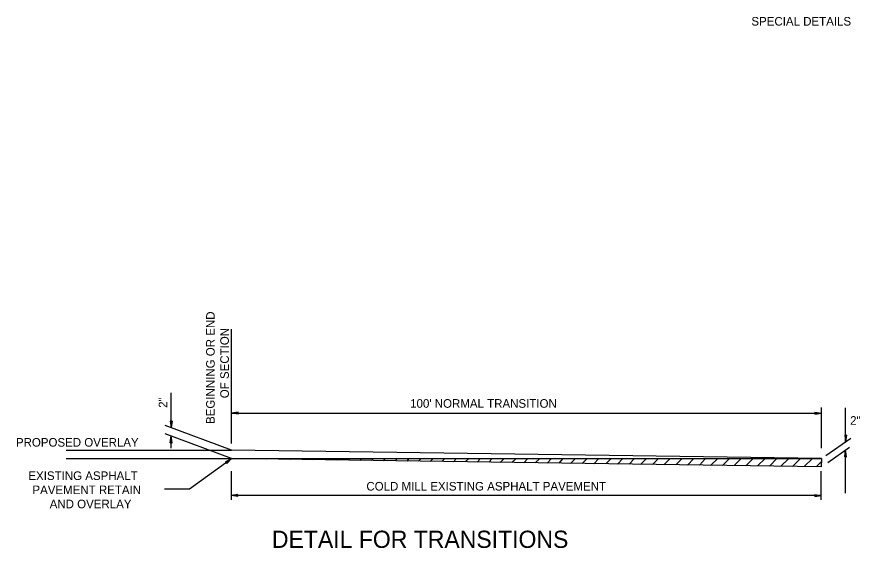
# Model space of a CAD drawing. Extents: x 1955770 to 1955917, y 566446 to 566544.
# Drawn here: x 1955852.8 to 1955911.7, y 566506.9 to 566544 of the extents above; entities that cross this region are included whole.
import ezdxf

# ---------------------------------------------------------------- set-up
doc = ezdxf.new("R2010")
doc.units = 0
doc.layers.add('Default', color=7, linetype='Continuous')
doc.layers.add('STAMP', color=7, linetype='Continuous')

msp = doc.modelspace()

# ---------------------------------------------------------------- linework, layer by layer
at = {"layer": 'Default'}
for p, q in [((1955867.799, 566514.22), (1955867.799, 566522.207)), ((1955863.58, 566515.354), (1955863.58, 566517.753)), ((1955868.266, 566516.42), (1955867.799, 566516.354)), ((1955867.799, 566516.354), (1955908.955, 566516.354)), ((1955868.266, 566516.287), (1955867.799, 566516.354)), ((1955868.266, 566516.398), (1955867.867, 566516.354)), ((1955868.266, 566516.287), (1955867.867, 566516.354)), ((1955868.266, 566516.398), (1955867.956, 566516.354)), ((1955868.266, 566516.309), (1955867.956, 566516.354)), ((1955868.266, 566516.376), (1955868.045, 566516.354)), ((1955868.266, 566516.309), (1955868.045, 566516.354)), ((1955868.266, 566516.376), (1955868.111, 566516.354)), ((1955868.266, 566516.332), (1955868.111, 566516.354)), ((1955868.266, 566516.354), (1955868.2, 566516.354)), ((1955868.266, 566516.332), (1955868.2, 566516.354)), ((1955868.266, 566516.287), (1955868.266, 566516.42)), ((1955908.488, 566516.42), (1955908.955, 566516.354)), ((1955908.488, 566516.42), (1955908.488, 566516.287)), ((1955908.488, 566516.398), (1955908.8, 566516.354)), ((1955908.488, 566516.398), (1955908.865, 566516.354)), ((1955908.488, 566516.376), (1955908.643, 566516.354)), ((1955908.488, 566516.376), (1955908.711, 566516.354)), ((1955908.488, 566516.287), (1955908.955, 566516.354)), ((1955908.488, 566516.332), (1955908.643, 566516.354)), ((1955908.488, 566516.309), (1955908.8, 566516.354)), ((1955908.488, 566516.287), (1955908.865, 566516.354)), ((1955908.488, 566516.309), (1955908.711, 566516.354)), ((1955908.488, 566516.332), (1955908.555, 566516.354)), ((1955908.488, 566516.354), (1955908.555, 566516.354)), ((1955908.955, 566513.911), (1955908.955, 566516.753)), ((1955910.642, 566514.354), (1955910.642, 566516.708)), ((1955863.513, 566515.799), (1955863.58, 566515.354)), ((1955863.513, 566515.799), (1955863.58, 566515.421)), ((1955863.646, 566515.799), (1955863.513, 566515.799)), ((1955863.536, 566515.799), (1955863.58, 566515.51)), ((1955863.536, 566515.799), (1955863.58, 566515.576)), ((1955863.558, 566515.799), (1955863.58, 566515.665)), ((1955863.558, 566515.799), (1955863.58, 566515.731)), ((1955863.646, 566515.799), (1955863.58, 566515.354)), ((1955863.602, 566515.799), (1955863.58, 566515.665)), ((1955863.625, 566515.799), (1955863.58, 566515.51)), ((1955863.625, 566515.799), (1955863.58, 566515.421)), ((1955863.602, 566515.799), (1955863.58, 566515.576)), ((1955863.58, 566515.799), (1955863.58, 566515.731)), ((1955867.799, 566513.755), (1955863.158, 566515.488)), ((1955867.799, 566513.178), (1955863.158, 566514.91)), ((1955863.513, 566514.288), (1955863.58, 566514.754)), ((1955863.513, 566514.288), (1955863.58, 566514.688)), ((1955863.536, 566514.288), (1955863.58, 566514.599)), ((1955863.536, 566514.288), (1955863.58, 566514.533)), ((1955863.646, 566514.288), (1955863.58, 566514.754)), ((1955863.58, 566513.911), (1955863.58, 566514.754)), ((1955863.625, 566514.288), (1955863.58, 566514.688)), ((1955863.625, 566514.288), (1955863.58, 566514.599)), ((1955863.602, 566514.288), (1955863.58, 566514.533)), ((1955909.266, 566513.4), (1955910.997, 566514.599)), ((1955910.576, 566514.82), (1955910.642, 566514.354)), ((1955910.709, 566514.82), (1955910.576, 566514.82)), ((1955910.599, 566514.82), (1955910.642, 566514.51)), ((1955910.599, 566514.82), (1955910.642, 566514.444)), ((1955910.619, 566514.82), (1955910.642, 566514.666)), ((1955910.619, 566514.82), (1955910.642, 566514.599)), ((1955910.709, 566514.82), (1955910.642, 566514.354)), ((1955910.664, 566514.82), (1955910.642, 566514.666)), ((1955910.687, 566514.82), (1955910.642, 566514.51)), ((1955910.709, 566514.82), (1955910.642, 566514.444)), ((1955910.687, 566514.82), (1955910.642, 566514.599)), ((1955910.642, 566514.82), (1955910.642, 566514.754)), ((1955910.664, 566514.82), (1955910.642, 566514.754)), ((1955863.513, 566514.288), (1955863.646, 566514.288)), ((1955863.558, 566514.288), (1955863.58, 566514.444)), ((1955863.558, 566514.288), (1955863.58, 566514.354)), ((1955863.602, 566514.288), (1955863.58, 566514.444)), ((1955863.58, 566514.288), (1955863.58, 566514.354)), ((1955909.399, 566512.911), (1955910.909, 566513.977)), ((1955856.252, 566513.754), (1955867.799, 566513.754)), ((1955908.955, 566513.178), (1955867.799, 566513.755)), ((1955910.576, 566513.311), (1955910.642, 566513.778)), ((1955910.576, 566513.311), (1955910.709, 566513.311)), ((1955910.599, 566513.311), (1955910.642, 566513.711)), ((1955910.599, 566513.311), (1955910.642, 566513.621)), ((1955910.619, 566513.311), (1955910.642, 566513.555)), ((1955910.619, 566513.311), (1955910.642, 566513.465)), ((1955910.642, 566510.757), (1955910.642, 566513.778)), ((1955910.709, 566513.311), (1955910.642, 566513.778)), ((1955910.709, 566513.311), (1955910.642, 566513.711)), ((1955910.687, 566513.311), (1955910.642, 566513.621)), ((1955910.687, 566513.311), (1955910.642, 566513.555)), ((1955910.664, 566513.311), (1955910.642, 566513.465)), ((1955910.664, 566513.311), (1955910.642, 566513.4)), ((1955910.642, 566513.311), (1955910.642, 566513.4)), ((1955856.252, 566513.177), (1955908.955, 566513.177)), ((1955864.869, 566511.068), (1955867.799, 566513.178)), ((1955867.378, 566512.955), (1955867.799, 566513.178)), ((1955867.378, 566512.955), (1955867.466, 566512.844)), ((1955867.401, 566512.955), (1955867.733, 566513.133)), ((1955867.401, 566512.955), (1955867.667, 566513.088)), ((1955867.401, 566512.933), (1955867.599, 566513.044)), ((1955867.401, 566512.933), (1955867.556, 566513)), ((1955867.423, 566512.911), (1955867.489, 566512.955)), ((1955867.423, 566512.911), (1955867.489, 566512.955)), ((1955867.445, 566512.866), (1955867.667, 566513.088)), ((1955867.445, 566512.889), (1955867.599, 566513.044)), ((1955867.445, 566512.889), (1955867.556, 566513)), ((1955867.466, 566512.844), (1955867.799, 566513.178)), ((1955867.466, 566512.866), (1955867.733, 566513.133)), ((1955908.932, 566512.599), (1955867.799, 566513.178)), ((1955869.42, 566513.155), (1955869.443, 566513.178)), ((1955870.231, 566513.144), (1955870.264, 566513.178)), ((1955871.042, 566513.132), (1955871.108, 566513.178)), ((1955871.873, 566513.121), (1955871.931, 566513.178)), ((1955872.685, 566513.109), (1955872.753, 566513.178)), ((1955873.496, 566513.098), (1955873.574, 566513.178)), ((1955874.306, 566513.087), (1955874.396, 566513.178)), ((1955875.136, 566513.075), (1955875.24, 566513.178)), ((1955875.947, 566513.064), (1955876.063, 566513.178)), ((1955876.779, 566513.051), (1955876.884, 566513.178)), ((1955877.569, 566513.041), (1955877.706, 566513.178)), ((1955878.402, 566513.029), (1955878.549, 566513.178)), ((1955879.211, 566513.017), (1955879.373, 566513.178)), ((1955880.042, 566513.006), (1955880.194, 566513.178)), ((1955880.831, 566512.995), (1955881.038, 566513.178)), ((1955881.665, 566512.983), (1955881.859, 566513.178)), ((1955882.476, 566512.972), (1955882.681, 566513.178)), ((1955883.286, 566512.959), (1955883.504, 566513.177)), ((1955884.096, 566512.948), (1955884.346, 566513.178)), ((1955884.928, 566512.937), (1955885.168, 566513.178)), ((1955885.738, 566512.925), (1955885.989, 566513.178)), ((1955886.549, 566512.914), (1955886.811, 566513.178)), ((1955887.358, 566512.903), (1955887.654, 566513.178)), ((1955888.191, 566512.891), (1955888.477, 566513.178)), ((1955888.978, 566512.88), (1955889.298, 566513.178)), ((1955889.812, 566512.868), (1955890.121, 566513.178)), ((1955890.644, 566512.857), (1955890.943, 566513.178)), ((1955891.454, 566512.845), (1955891.786, 566513.178)), ((1955892.265, 566512.834), (1955892.608, 566513.178)), ((1955893.076, 566512.823), (1955893.43, 566513.178)), ((1955893.909, 566512.811), (1955894.274, 566513.178)), ((1955894.719, 566512.8), (1955895.096, 566513.178)), ((1955895.529, 566512.788), (1955895.918, 566513.178)), ((1955896.338, 566512.776), (1955896.738, 566513.178)), ((1955897.171, 566512.765), (1955897.583, 566513.178)), ((1955897.96, 566512.754), (1955898.405, 566513.178)), ((1955898.792, 566512.742), (1955899.227, 566513.178)), ((1955899.603, 566512.731), (1955900.048, 566513.178)), ((1955900.434, 566512.719), (1955900.871, 566513.178)), ((1955901.222, 566512.707), (1955901.714, 566513.178)), ((1955902.054, 566512.696), (1955902.536, 566513.178)), ((1955902.87, 566512.689), (1955903.358, 566513.178)), ((1955903.676, 566512.673), (1955904.18, 566513.178)), ((1955904.486, 566512.662), (1955905.023, 566513.178)), ((1955905.318, 566512.65), (1955905.845, 566513.178)), ((1955906.129, 566512.639), (1955906.668, 566513.178)), ((1955906.94, 566512.627), (1955907.488, 566513.178)), ((1955907.749, 566512.616), (1955908.333, 566513.178)), ((1955908.582, 566512.604), (1955908.947, 566512.968)), ((1955908.955, 566513.178), (1955908.932, 566512.599)), ((1955867.799, 566510.312), (1955867.799, 566512.311)), ((1955908.932, 566510.312), (1955908.932, 566512.311)), ((1955863.115, 566511.068), (1955864.869, 566511.068)), ((1955868.246, 566510.667), (1955867.799, 566510.602)), ((1955868.246, 566510.667), (1955867.799, 566510.602)), ((1955908.932, 566510.602), (1955867.799, 566510.602)), ((1955868.246, 566510.534), (1955867.799, 566510.602)), ((1955868.246, 566510.534), (1955867.799, 566510.602)), ((1955868.246, 566510.667), (1955867.867, 566510.602)), ((1955868.246, 566510.667), (1955867.867, 566510.602)), ((1955868.246, 566510.557), (1955867.867, 566510.602)), ((1955868.246, 566510.557), (1955867.867, 566510.602)), ((1955868.246, 566510.647), (1955867.956, 566510.602)), ((1955868.246, 566510.647), (1955867.956, 566510.602)), ((1955868.246, 566510.557), (1955867.956, 566510.602)), ((1955868.246, 566510.557), (1955867.956, 566510.602)), ((1955868.246, 566510.647), (1955868.022, 566510.602)), ((1955868.246, 566510.647), (1955868.022, 566510.602)), ((1955868.246, 566510.579), (1955868.022, 566510.602)), ((1955868.246, 566510.579), (1955868.022, 566510.602)), ((1955868.246, 566510.622), (1955868.111, 566510.602)), ((1955868.246, 566510.622), (1955868.111, 566510.602)), ((1955868.246, 566510.579), (1955868.111, 566510.602)), ((1955868.246, 566510.579), (1955868.111, 566510.602)), ((1955868.246, 566510.622), (1955868.178, 566510.602)), ((1955868.246, 566510.622), (1955868.178, 566510.602)), ((1955868.246, 566510.602), (1955868.178, 566510.602)), ((1955868.246, 566510.602), (1955868.178, 566510.602)), ((1955868.246, 566510.534), (1955868.246, 566510.667)), ((1955868.246, 566510.534), (1955868.246, 566510.667)), ((1955908.488, 566510.667), (1955908.932, 566510.602)), ((1955908.488, 566510.667), (1955908.865, 566510.602)), ((1955908.488, 566510.667), (1955908.488, 566510.534)), ((1955908.488, 566510.647), (1955908.777, 566510.602)), ((1955908.488, 566510.647), (1955908.711, 566510.602)), ((1955908.488, 566510.622), (1955908.622, 566510.602)), ((1955908.488, 566510.622), (1955908.555, 566510.602)), ((1955908.488, 566510.534), (1955908.932, 566510.602)), ((1955908.488, 566510.579), (1955908.622, 566510.602)), ((1955908.488, 566510.557), (1955908.777, 566510.602)), ((1955908.488, 566510.557), (1955908.865, 566510.602)), ((1955908.488, 566510.579), (1955908.711, 566510.602)), ((1955908.488, 566510.602), (1955908.555, 566510.602))]:
    msp.add_line(p, q, dxfattribs=at)

# ---------------------------------------------------------------- texts
for s, p in [('BEGINNING OR END', (1955866.626, 566515.593)), ('OF SECTION', (1955867.612, 566517.388)), ('2"', (1955863.314, 566516.72))]:
    msp.add_text(s, height=0.6, rotation=90, dxfattribs=at).set_placement(p)
for s, height, p in [("100' NORMAL TRANSITION", 0.6, (1955880.26, 566516.723)), ('2"', 0.6, (1955910.955, 566515.537)), ('PROPOSED OVERLAY', 0.6, (1955852.756, 566514.011)), ('EXISTING ASPHALT', 0.6, (1955853.625, 566511.684)), ('COLD MILL EXISTING ASPHALT PAVEMENT', 0.6, (1955877.206, 566510.948)), ('PAVEMENT RETAIN', 0.6, (1955853.908, 566510.698)), ('AND OVERLAY', 0.6, (1955855.112, 566509.712)), ('DETAIL FOR TRANSITIONS', 1.2, (1955870.613, 566506.95))]:
    msp.add_text(s, height=height, dxfattribs=at).set_placement(p)
at = {"layer": 'STAMP'}
msp.add_text('SPECIAL DETAILS', height=0.6, rotation=360, dxfattribs=at).set_placement((1955904.066, 566543.379))

doc.saveas('drawing.dxf')
